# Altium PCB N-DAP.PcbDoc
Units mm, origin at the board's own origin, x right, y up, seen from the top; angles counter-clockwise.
Board outline 25.4 x 15.48 mm, 4 copper layers (Top Layer, GND PLANE, Signal Layer 1, Bottom Layer), stack 1.577 mm thick; 35 components, 41 nets, 128 pads, 69 vias.
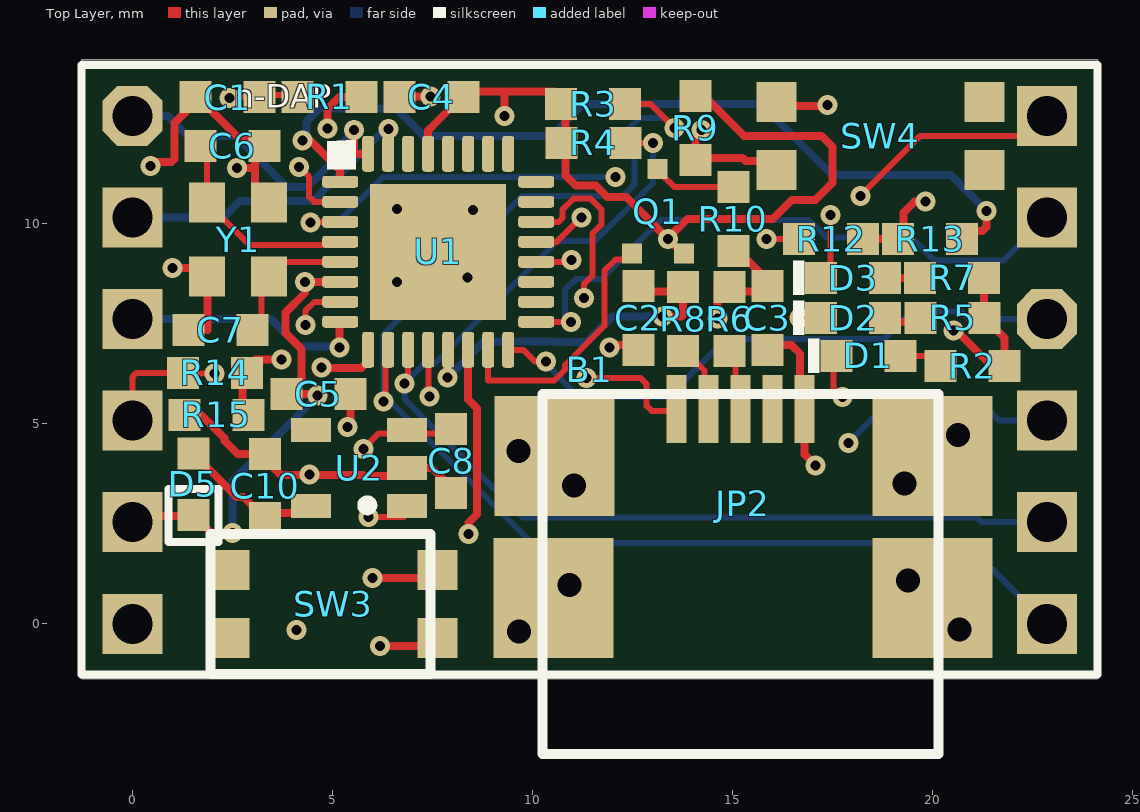
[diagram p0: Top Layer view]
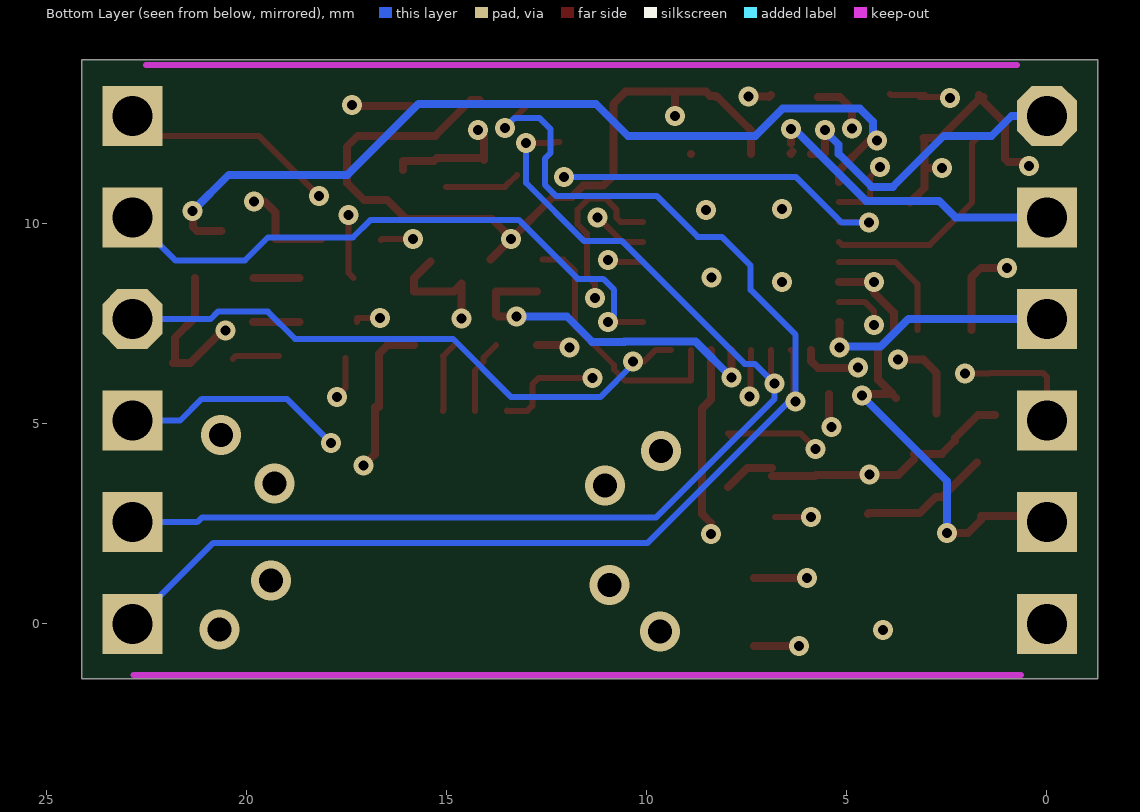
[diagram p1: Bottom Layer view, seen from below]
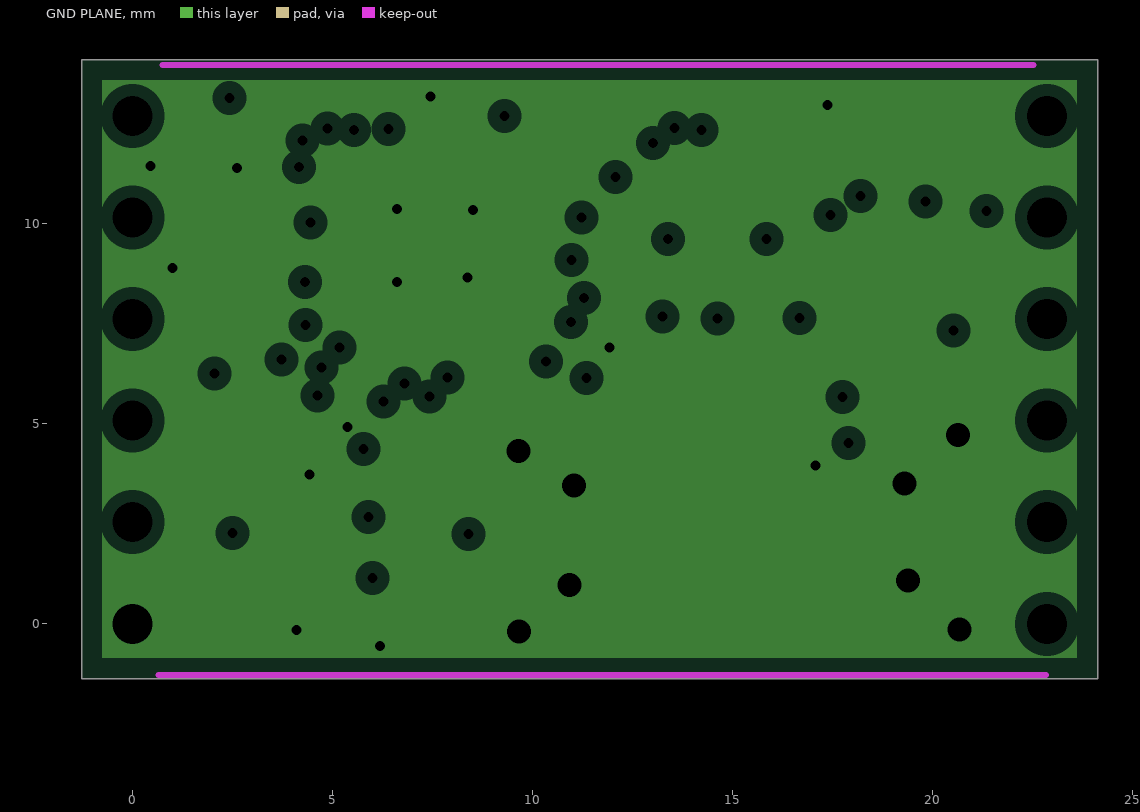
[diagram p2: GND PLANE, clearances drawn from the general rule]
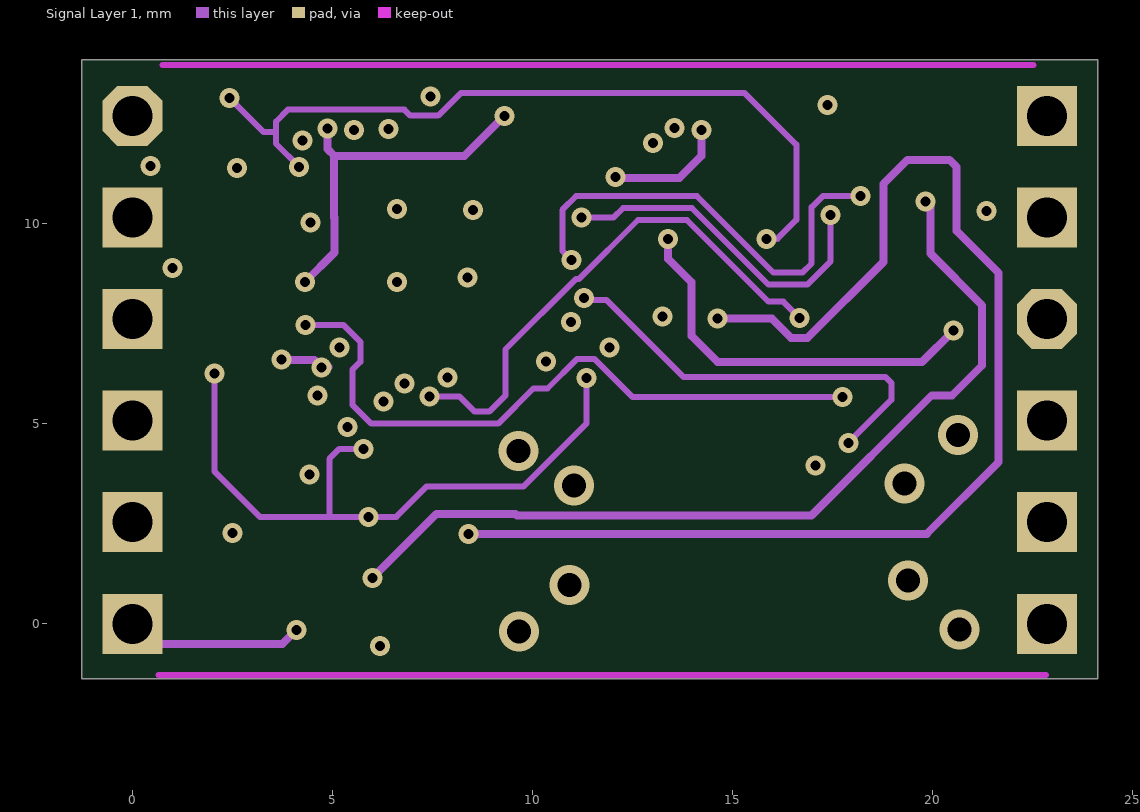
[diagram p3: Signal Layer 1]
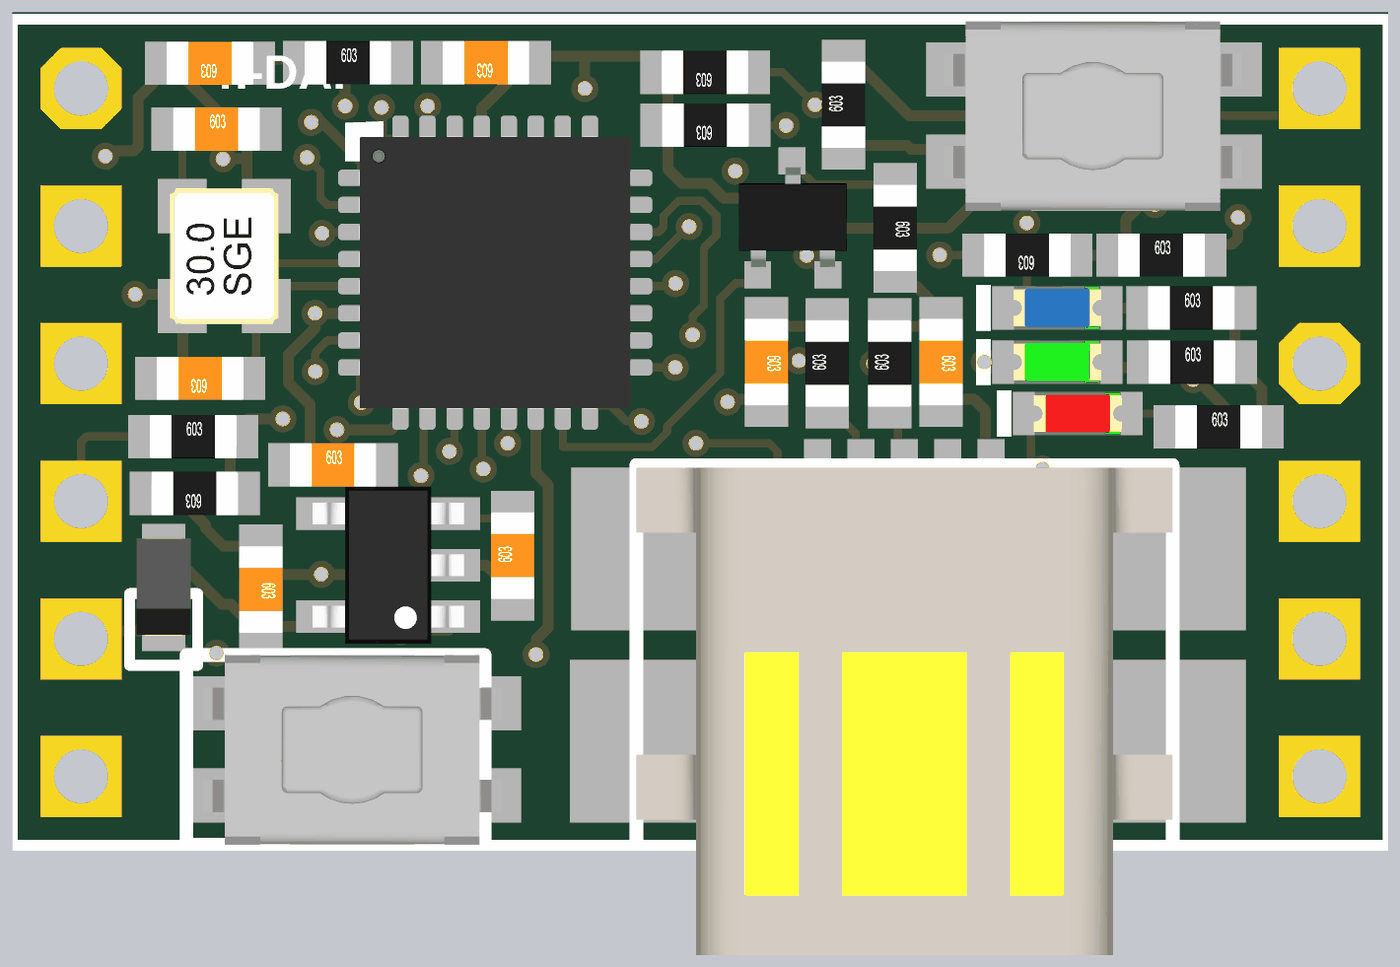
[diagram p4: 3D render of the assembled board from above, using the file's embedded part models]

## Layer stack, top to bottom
Top Solder: solder mask 0.0102, Solder Resist, Dk 3.5
Top Layer: signal copper 0.0356
Dielectric1: core 0.48, FR-4, Dk 4.8
GND PLANE: plane copper 0.036, net GND
Dielectric 4: prepreg 0.7, Dk 4.2
Signal Layer 1: signal copper 0.036
Dielectric 3: core 0.254, Dk 4.2
Bottom Layer: signal copper 0.0356
Bottom Solder: solder mask 0.0102, Solder Resist, Dk 3.5

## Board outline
-1.27,-1.37 24.13,-1.37 24.13,14.105 -1.27,14.105

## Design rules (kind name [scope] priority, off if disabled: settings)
Clearance "Clearance IN CLASS 1mm" [(InNetClass('CL-1mm'))] p1 off: gap=1 ignorepadtopadclearanceinfootprint=FALSE except(0: Arc-Hole Track-Hole SMDPad-Hole THPad-Hole Via-Hole Fill-Hole Poly-Hole Region-Hole Text-Hole)
Clearance Clearance_GND_PLANE [InNamedPolygon('GND_POLY_TOP')] p2 off: gap=0.4 ignorepadtopadclearanceinfootprint=FALSE except(0: Arc-Hole Track-Hole SMDPad-Hole THPad-Hole Via-Hole Fill-Hole Poly-Hole Region-Hole Text-Hole)
Clearance Clearance_+5V_POLY [InNamedPolygon('poly_+5V-bottom')] p3 off: gap=0.5 ignorepadtopadclearanceinfootprint=FALSE except(0: Arc-Hole Track-Hole SMDPad-Hole THPad-Hole Via-Hole Fill-Hole Poly-Hole Region-Hole Text-Hole)
Clearance [All] p4: gap=0.15 ignorepadtopadclearanceinfootprint=FALSE except(0: Arc-Hole Track-Hole SMDPad-Hole THPad-Hole Via-Hole Fill-Hole Poly-Hole Region-Hole Text-Hole)
MinimumAnnularRing [All] p1: minimumring=0.149
PlaneClearance [All] p1: clearance=0.3
PlaneConnect Plane_ConnectStyle_1 [(Name = 'C1-1') Or (Name = 'C1-2') Or (Name = 'C2-1') Or (Name = 'C2-2') Or (Name = 'C3-1') Or (Name = 'C3-2') Or (Name = 'C4-1') Or (Name = 'C4-2') Or (Name = 'C5-1') Or (Name = 'C5-2') Or (Name = 'C6-1') Or (Name = 'C6-2') Or (Name = 'C7-1')] p1 off: planeconnectstyle=Relief reliefexpansion=1.27 reliefentries=4 reliefconductorwidth=0.381 reliefairgap=0.508
PlaneConnect [All] p2: planeconnectstyle=Direct reliefexpansion=0.635 reliefentries=4 reliefconductorwidth=0.305 reliefairgap=0.254
PolygonConnect [All] p1: connectstyle=Direct reliefconductorwidth=0.254 reliefentries=4 polygonreliefangle="90 Angle" airgapwidth=0.254
RoomDefinition N-DAP [InComponentClass('N-DAP')] p1: confinementstyle=ConfineIn formatcopy=TRUE lockcomponents=FALSE outline -10.705,41.255 28.03,41.255 28.03,-1.925 -10.705,-1.925
RoutingVias VIASWITDTH2MM [(InNetClass('W-2mm'))] p1 off: holewidth=1 width=1.8 viastyle="Through Hole" minholewidth=0.4 minwidth=0.7 maxholewidth=1 maxwidth=1.8
RoutingVias VIASWITDTH1MM [(InNetClass('W-2mm'))] p2 off: holewidth=0.5 width=1 viastyle="Through Hole" minholewidth=0.5 minwidth=1 maxholewidth=0.5 maxwidth=1
RoutingVias VIASWITDTH1.5MM [(InNetClass('W-2mm'))] p3 off: holewidth=0.9 width=1.4 viastyle="Through Hole" minholewidth=0.9 minwidth=1.4 maxholewidth=0.9 maxwidth=1.4
RoutingVias [All] p4: holewidth=0.2 width=0.5 viastyle="Through Hole" minholewidth=0.2 minwidth=0.5 maxholewidth=4 maxwidth=2
SilkToSolderMaskClearance SilkscreenOverComponentPads [IsPad] p1: minsilkscreentomaskgap=0.254 clearancetoexposedcopper=TRUE
SolderMaskExpansion [All] p1: expansion=0
Width 12V_PLANE [(InNet('+12V')) and (IsPolygon)] p1 off: maxlimit=0.3 minlimit=0.2 preferedwidth=0.2
Width GND_PLANE [(InNet('GND'))  and (IsPolygon)] p2 off: maxlimit=0.3 minlimit=0.2 preferedwidth=0.2
Width WIDTH2MM [(InNetClass('W-2mm'))] p3 off: maxlimit=2 minlimit=0.25 preferedwidth=2
Width WIDTH1.5MM [(InNetClass('W-1.5mm'))] p4 off: maxlimit=2 minlimit=0.5 preferedwidth=1.5
Width "WIDTH 1MM" [(InNetClass('W-1mm'))] p5 off: maxlimit=2 minlimit=0.75 preferedwidth=1
Width WIDTH0.5MM [(InNetClass('W-0.5mm'))] p6 off: maxlimit=2 minlimit=0.25 preferedwidth=0.5
Width WIDTH0.25MM [(InNetClass('W-0.25mm'))] p7 off: maxlimit=2 minlimit=0.2 preferedwidth=0.25
Width [All] p8: maxlimit=2 minlimit=0.149 preferedwidth=0.15
27 further rules are at their usual default settings.

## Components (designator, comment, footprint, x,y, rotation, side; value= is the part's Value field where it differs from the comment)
B1 "N-DAP" N-DAP 0,12.7 r0 top locked
C1 "100nF" 0603_CAP 2.38,13.165 r180 top
C2 "18pF" 0603_CAP 12.65,7.65 r270 top
C3 "18pF" 0603_CAP 15.875,7.65 r270 top
C4 "100nF" 0603_CAP 7.475,13.175 r180 top
C5 "100nF" 0603_CAP 4.65,5.75 r0 top
C6 "33pF" 0603_CAP 2.5,11.95 r0 top
C7 "33pF" 0603_CAP 2.2,7.35 r180 top
C8 "1uF/MLCC" 0603_CAP 7.97,4.075 r90 top
C10 "1uF/MLCC" 0603_CAP 3.32,3.45 r270 top
D1 "LED_RED_0603" 0603_LED_RED 18.4,6.7 r180 top
D2 "LED_GRN_0603" 0603_LED_GRN 18.02,7.65 r180 top
D3 "LED_BLU_0603" 0603_LED_BLU 18.02,8.65 r180 top
D5 "NSR20F30NXT5G" 0603_DIODE-CDSU101A 1.525,3.5 r270 top
JP2 "USB-MINI-B" USB-MINI-B-HIR-UX60A-MB-5ST 16.85,4.55 r180 top
Q1 "BSS84,215" SOT323/SC70-3_SMALL 13.125,10.35 r180 top
R1 "10K" 0603_RES 4.925,13.175 r0 top
R2 "680R" 0603_RES 21,6.45 r0 top
R3 "10K" 0603_RES 11.52,13 r180 top
R4 "10K" 0603_RES 11.525,12.025 r180 top
R5 "470R" 0603_RES 20.505,7.65 r0 top
R6 "33R" 0603_RES 14.925,7.625 r90 top
R7 "470R" 0603_RES 20.495,8.65 r0 top
R8 "33R" 0603_RES 13.77,7.625 r90 top
R9 "10K" 0603_RES 14.075,12.4 r90 top
R10 "1.5K" 0603_RES 15.025,10.125 r270 top
R12 "0R" 0603_RES 17.47,9.625 r180 top
R13 "N.A." 0603_RES 19.945,9.625 r0 top
R14 "10K" 0603_RES 2.07,6.275 r0 top
R15 "18K" 0603_RES 2.1,5.225 r180 top
SW3 "EVQ-P2202M" BUTTON_4.7x3.5mm 5.125,0.35 r90 top
SW4 "EVQ-P2202M" BUTTON_4.7x3.5mm 18.8,12.05 r90 top
U1 "LPC11U35FHI33/501" QFN32_0.5MM_PAD 7.645,9.3 r0 top
U2 "TPS78233" SOT23-5_0.95MM-NOSILK 5.67,3.9 r90 top
Y1 "12MHz" CRY-SMD4-2.5X2MM 2.645,9.605 r90 top

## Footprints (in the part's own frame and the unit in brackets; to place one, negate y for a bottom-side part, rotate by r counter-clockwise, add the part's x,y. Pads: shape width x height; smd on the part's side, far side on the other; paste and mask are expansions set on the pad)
0603_CAP [mm]
  rect 0.8x0.8 smd mask+0: 1(-0.8,0) 2(0.8,0)
  body extent -0.8,-0.4 0.8,0.4, height 0.3
0603_DIODE-CDSU101A [mm]
  rect 0.8x0.8 smd mask+0: 1(-0.76,0) 2(0.786,0)
  silkscreen extent 0.13,-0.63 1.45,0.63, body extent -0.9,-0.5 0.9,0.5, height 0.85
0603_LED_BLU [mm]
  rect 0.8x0.8 smd mask+0: 1(-0.8,0) 2(0.8,0)
  silkscreen extent 1.22,-0.43 1.5,0.43, body extent -0.81,-0.4 0.81,0.4, height 0.6
0603_LED_GRN [mm]
  rect 0.8x0.8 smd mask+0: 1(-0.8,0) 2(0.8,0)
  silkscreen extent 1.22,-0.43 1.5,0.43, body extent -0.81,-0.4 0.81,0.4, height 0.6
0603_LED_RED [mm]
  rect 0.8x0.8 smd mask+0: 1(-0.8,0) 2(0.8,0)
  silkscreen extent 1.22,-0.43 1.5,0.43, body extent -0.81,-0.4 0.81,0.4, height 0.6
0603_RES [mm]
  rect 0.8x0.8 smd mask+0: 1(-0.8,0) 2(0.8,0)
  body extent -0.8,-0.4 0.8,0.4, height 0.3
BUTTON_4.7x3.5mm [mm] "TACTILE BUTTON 4.7x3.5mm Panasonic EVQ-P2202M"
  rect 1x1 smd: 1(-0.7,2.7) 2(1,2.7) 3(-0.7,-2.5) 4(1,-2.5)
  body extent -1.61,-2.63 1.89,2.87, height 2.15
CRY-SMD4-2.5X2MM [mm]
  rect 1x0.9 smd: 1(-0.925,-0.775) 2(0.925,-0.775) 3(0.925,0.775) 4(-0.925,0.775)
  body extent -1.35,-1.1 1.35,1.1, height 0.55
N-DAP [mm]
  oct 1.5x1.5 hole 1: 1(0,0) 10(22.86,-5.08)
  rect 1.5x1.5 hole 1: 2(0,-2.54) 3(0,-5.08) 4(0,-7.62) 5(0,-10.16) 6(0,-12.7) 7(22.86,-12.7) 8(22.86,-10.16) 9(22.86,-7.62) 11(22.86,-2.54) 12(22.86,0)
  silkscreen extent -1.27,-15.95 24.13,1.28, body extent 1.54,-4.44 121.83,177.96, height 0.55
QFN32_0.5MM_PAD [mm]
  rrect50% 0.9x0.3 smd mask+0: 1(-2.45,1.75) 2(-2.45,1.25) 3(-2.45,0.75) 4(-2.45,0.25) 5(-2.45,-0.25) 6(-2.45,-0.75) 7(-2.45,-1.25) 8(-2.45,-1.75) 17(2.45,-1.75) 18(2.45,-1.25) 19(2.45,-0.75) 20(2.45,-0.25) 21(2.45,0.25) 22(2.45,0.75) 23(2.45,1.25) 24(2.45,1.75)
  rrect50% 0.3x0.9 smd mask+0: 9(-1.75,-2.45) 10(-1.25,-2.45) 11(-0.75,-2.45) 12(-0.25,-2.45) 13(0.25,-2.45) 14(0.75,-2.45) 15(1.25,-2.45) 16(1.75,-2.45) 25(1.75,2.45) 26(1.25,2.45) 27(0.75,2.45) 28(0.25,2.45) 29(-0.25,2.45) 30(-0.75,2.45) 31(-1.25,2.45) 32(-1.75,2.45)
  rect 3.4x3.4 smd: 33(0,0)
  silkscreen extent -2.77,2.06 -2.06,2.79, body extent -2.51,-2.51 2.51,2.51, height 0.8
SOT23-5_0.95MM-NOSILK [mm]
  rect 0.6x1 smd: 1(-0.95,-1.2) 2(0,-1.2) 3(0.95,-1.2) 4(0.95,1.2) 5(-0.95,1.2)
  silkscreen extent -1.06,-0.33 -0.81,-0.08, body extent -1.45,-1.4 1.45,1.4, height 1.45
SOT323/SC70-3_SMALL [mm]
  rect 0.5x0.5 smd: 1(0.635,1.092) 2(-0.66,1.092) 3(0,-1.016)
  body extent -1.02,-1.02 0.98,1.08, height 1
USB-MINI-B-HIR-UX60A-MB-5ST [mm]
  rect 0.5x1.7 smd: 1(3.25,-0.825) 2(2.45,-0.825) 3(1.65,-0.825) 4(0.85,-0.825) 5(0.05,-0.825)
  rect 3x3 smd: 6(-3.15,3.9) 7(6.325,3.9) 8(-3.15,0.35) 9(6.3,0.35)
  body extent -3.3,-1.15 6.6,7.85, height 4.6

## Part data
C1 C4 C5: library part C, "CAPACITOR", Supplier Part Number 1=581-06035C104KAT2A
C2 C3: library part C, "CAPACITOR", Supplier Part Number 1=581-02013A180GAT2A
C6 C7: library part C, "CAPACITOR", Supplier Part Number 1=581-06035A330J
C8 C10: library part C, "CAPACITOR", Supplier Part Number 1=81-GCM188R71C105K64D
D1: library part LED, Supplier Part Number 1="Mouser - 720-LSL29K-G1J2-1-Z"
D2: library part LED, Supplier Part Number 1=720-LGL29KF2J124Z
D3: library part LED, Supplier Part Number 1=720-LBQ39GL2N2351
D5: library part DIODE, "DIODE", Supplier Part Number 1=863-NSR20F30NXT5G
JP2: Supplier Part Number 1=798-UX60A-MB-5ST
Q1: library part "mosfet BSS84", "POWER MOSFET-P SOT23", Supplier Part Number 1=621-BSS84W-F
R1 R3 R4 R9 R14: library part R, "RESISTOR", Supplier Part Number 1=667-ERJ-3EKF1002V
R2: library part R, "RESISTOR", Supplier Part Number 1=754-RR0816P-681D
R5 R7: library part R, "RESISTOR", Supplier Part Number 1=667-ERJ-3EKF4700V
R6 R8: library part R, "RESISTOR", Supplier Part Number 1=667-ERJ-3EKF33R0V
R10: library part R, "RESISTOR", Supplier Part Number 1=667-ERJ-3EKF1501V
R12 R13: library part R, "RESISTOR", Supplier Part Number 1=667-ERJ-3GEY0R00V
R15: library part R, "RESISTOR", Supplier Part Number 1=667-ERJ-3GEYJ183V
SW3 SW4: library part BUTTON_TACT, "BUTTON TACTILE", Supplier Part Number 1=667-EVQ-P2202M
U1: Supplier Part Number 1=771-LPC11U35FHI33501
U2: library part NCP702N, Supplier Part Number 1=595-TPS78233DDCR
Y1: library part XTAL_4PINS, "CRYSTAL", Supplier Part Number 1=717-8Z-12.000MAAJ-T

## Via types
v1: diameter 0.5, hole 0.25, Top Layer to Bottom Layer, tented both sides, 61 vias
v2: diameter 1, hole 0.6, Top Layer to Bottom Layer, tented both sides, 8 vias

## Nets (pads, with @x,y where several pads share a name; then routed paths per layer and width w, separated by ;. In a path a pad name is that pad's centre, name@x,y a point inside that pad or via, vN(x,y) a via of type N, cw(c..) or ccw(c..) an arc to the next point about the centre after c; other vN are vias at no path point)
3.3V: B1.5 C4.1 C5.1 D5.2 Q1.2 R1.2 R2.2 R3.2 R4.2 R5.2 R7.2 R9.2 U1.6 U1.29 | length 57.2
  Top Layer w0.2: B1.5@0,2.04 0.649,2.689 D5.2@1.65,2.689 ; D5.2@1.65,2.589 1.964,2.275 v1(2.5,2.275) ; C5.1@3.775,5.65 4.225,6.1 C5.1@4.225,6.125 ; C5.1@3.875,5.75 4.575,5.75 v1@4.625,5.7 ; C5.1@3.875,5.775 C5.1@4.225,6.125 ; v1(4.875,12.376) 4.875,12.875 5.175,13.175 R1.2 ; U1.6 v1(4.32,8.55) 4.32,8.276 3.825,7.781 3.825,7.268 4.225,6.868 C5.1@4.225,6.125 ; U1.29 7.395,12.335 7.46,12.4 ; 7.45,12.4 7.46,12.4 ; C4.1 8.235,13.175 7.46,12.4 ; C4.1@8.275,13.2 8.42,13.2 8.521,13.301 10.534,13.301 10.834,13 10.834,11.209 11.092,10.951 11.592,10.951 11.868,10.675 12.338,10.675 v1@13.382,9.632 ; v1(9.3,12.7) 9.3,13.275 9.325,13.3 ; v1@13.375,9.625 v1@13.382,9.632 ; Q1.2@13.905,9.108 v1(13.395,9.618) v1@13.382,9.632 ; R9.2@14.177,13.098 14.389,13.098 15.287,12.2 17.225,12.2 17.5,11.925 17.5,11.025 17.075,10.6 16.491,10.6 16.016,10.125 13.875,10.125 v1@13.382,9.632 ; v1(20.526,7.325) 20.603,7.325 21.404,6.525 R2.2@21.8,6.525 ; R7.2 21.295,7.655 21.8,7.15 R2.2@21.8,6.525 ; R2.2@21.85,6.525 R2.2@21.8,6.525
  Signal Layer 1 w0.2: v1(4.32,8.55) 5.05,9.28 5.05,10.157 5.045,10.162 5.045,11.7 ; v1(4.875,12.376) 4.875,11.87 5.045,11.7 ; v1(9.3,12.7) 8.3,11.7 5.045,11.7 ; v1(13.395,9.618) 13.395,9.118 13.975,8.538 13.975,7.2 14.634,6.541 19.742,6.541 v1(20.526,7.325)
  Bottom Layer w0.2: v1(2.5,2.275) 2.5,3.575 v1(4.625,5.7)
3.3V1: C10.2 D5.1 U2.5 | length 3.3
  Top Layer w0.2: D5.1@1.745,4.035 2.605,3.175 2.77,3.175 3.181,2.764 3.32,2.764 4.456,2.764 U2.5@4.47,2.75
ADC0: B1.12 U1.20 | length 18
  Top Layer w0.15: U1.20 10.925,9.05 v1(10.975,9.1) ; v1(18.2,10.7) 19.7,12.2 22.8,12.2 22.86,12.26 B1.12
  Signal Layer 1 w0.15: v1(10.975,9.1) 10.751,9.324 10.751,10.347 11.096,10.693 14.11,10.693 16.028,8.775 16.75,8.775 16.982,9.008 16.982,10.414 17.268,10.7 v1(18.2,10.7)
ADC1: B1.9 U1.22 | length 20.7
  Top Layer w0.15: U1.22 10.657,10.05 10.751,10.143 10.751,10.347 11.029,10.626 11.458,10.626 11.731,10.352 11.731,9.984 11.5,9.753 11.5,8.7 11.289,8.489 v1(11.289,8.15)
  Signal Layer 1 w0.15: v1(11.289,8.15) 11.289,8.139 11.25,8.1 11.85,8.1 13.775,6.175 18.825,6.175 18.975,6.025 18.975,5.6 v1(17.9,4.525)
  Bottom Layer w0.15: v1(17.9,4.525) 19,5.625 21.125,5.625 21.67,5.08 B1.9
ADC2: U1.23
ADC3: U1.24
ADC5/SWDIO: U1.25
BLUE: D3.2 U1.21 | length 11.5
  Top Layer w0.15: U1.21 10.611,9.55 11.211,10.151 v1(11.226,10.151) ; D3.2@17.334,8.65 17.457,8.773 v1(17.457,10.218)
  Signal Layer 1 w0.15: v1(11.226,10.151) 12.026,10.151 12.268,10.393 13.986,10.393 15.904,8.475 16.874,8.475 17.457,9.058 v1(17.457,10.218)
GND: B1.6 C1.2 C2.2 C3.2 C4.2 C5.2 C6.2 C7.2 C8.1 C10.1 JP2.5 JP2.6 JP2.7 JP2.8 JP2.9 R15.2 SW3.3 SW4.2 U1.33 U2.2 Y1.2 Y1.4 | length 29.5
  Top Layer w0.2: v1@0.45,11.425 v1(0.45,11.45) 0.55,11.55 0.975,11.55 1.05,11.625 1.05,12.52 C1.2@1.667,13.137 ; v1(1,8.9) 1.65,8.9 1.884,8.666 1.884,7.35 ; R15.2 1.714,5.225 2.3,4.639 2.3,4.575 2.625,4.25 C10.1 ; C1.2 1.639,13.165 C1.2@1.667,13.137 ; C1.2@1.695,13.22 1.695,13.165 C1.2@1.667,13.137 ; v1@2.595,11.425 v1(2.62,11.4) 3.062,11.4 ; C6.2@3.062,12.15 3.062,11.4 ; C6.2@3.081,12.15 2.654,12.15 C1.2@1.667,13.137 ; C10.1@3.32,4.11 3.705,3.725 v1@4.44,3.725 ; Y1.2 3.062,10.888 3.062,11.4 ; v1(4.434,3.73) v1@4.44,3.725 ; v1(5.375,4.925) 5.45,5 C5.2 ; v1(6.195,-0.55) SW3.3@7.32,-0.55 ; U2.2@6.87,3.7 5.795,3.7 5.77,3.725 v1@4.44,3.725 ; U2.2 7.485,3.9 C8.1@7.97,3.415 ; C4.2@6.9,13.22 6.945,13.175 v1(7.45,13.176) ; v1(11.933,6.912) 11.986,6.964 C2.2@12.745,6.964 ; C3.2@15.82,6.964 16.48,6.964 16.695,6.749 JP2.5@16.695,5.425 ; SW4.2@15.895,12.95 17.35,12.95 v1(17.375,12.975) ; JP2.5@16.8,5.425 16.8,4.237 v1(17.081,3.956)
  Signal Layer 1 w0.2: B1.6@0,-0.5 3.75,-0.5 v1(4.1,-0.15)
  other v1: 6.62,8.55 8.375,8.65 8.52,10.35 6.62,10.375
  other v2: 9.67,-0.193 20.68,-0.138 10.933,0.969 19.396,1.079 11.041,3.454 19.306,3.507 9.65,4.325 20.64,4.719
GREEN: D2.2 U1.12 | length 14.9
  Top Layer w0.15: U1.12 7.388,6.843 7.388,6.485 7.4,6.472 7.4,5.7 v1(7.425,5.675) ; v1(16.675,7.65) 17.234,7.65 17.25,7.634 D2.2@17.25,7.55
  Signal Layer 1 w0.15: v1(7.425,5.675) 8.182,5.675 8.557,5.3 8.922,5.3 9.325,5.703 9.325,6.858 11.092,8.625 11.172,8.625 12.64,10.093 13.862,10.093 15.904,8.05 16.275,8.05 v1(16.675,7.65)
LPC11-D+: JP2.3 R6.1 | length 1.8
  Top Layer w0.15: R6.1@14.82,6.965 15.095,6.69 15.079,6.673 15.079,5.346 15.095,5.33 JP2.3@15.1,5.325
LPC11-D-: JP2.2 R8.1 | length 1.9
  Top Layer w0.15: R8.1@13.77,6.965 R8.1@14.082,6.653 ; R8.1@14.078,6.648 14.082,6.644 14.082,6.551 14.3,6.333 14.3,5.425 JP2.2@14.3,5.325
LPC11-USBD+: C3.1 R6.2 R10.2 U1.14 | length 38.9
  Top Layer w0.2: U1.14 8.395,5.604 8.62,5.379 8.62,2.745 8.4,2.525 v1(8.4,2.25) ; v1(14.626,7.625) 14.626,8.505 14.82,8.311 C3.1@15.82,8.311 ; R10.2@15.41,9.053 15.82,8.643 C3.1@15.82,8.31
  Signal Layer 1 w0.2: v1(8.4,2.25) 19.861,2.25 21.65,4.039 21.65,8.775 20.6,9.825 20.6,11.425 20.425,11.6 19.375,11.6 18.775,11 18.775,9.043 16.882,7.15 16.468,7.15 15.993,7.625 v1(14.626,7.625)
LPC11-USBD-: C2.1 R8.2 U1.13 | length 8.9
  Top Layer w0.2: v1(7.875,6.15) 7.875,6.83 U1.13 ; C2.1@12.745,8.311 13.77,8.311 13.77,7.721 13.725,7.675 v1(13.251,7.675)
  Bottom Layer w0.2: v1(7.875,6.15) 8.779,7.054 10.552,7.054 10.555,7.05 11.365,7.05 11.99,7.675 v1(13.251,7.675)
LPC11-USBSCON: Q1.1 U1.15 | length 6.6
  Top Layer w0.15: U1.15 8.895,6.08 8.896,6.079 10.541,6.079 10.82,6.357 10.82,6.47 11.8,7.45 11.8,8.824 12.084,9.108 Q1.1@12.61,9.108
LPC11-USBVBUS: R14.2 R15.1 U1.9 | length 4.9
  Top Layer w0.2: R15.1@2.756,5.25 2.756,6.275 3.081,6.6 v1(3.725,6.6) ; v1@4.751,6.4 5.725,6.4 5.895,6.57 U1.9
  Signal Layer 1 w0.2: v1(3.725,6.6) 4.551,6.6 v1@4.75,6.4 ; v1(4.725,6.4) v1@4.75,6.4 ; v1@4.9,6.425 4.875,6.4 v1@4.75,6.4
MOSI0: U1.18
NetD1_1: D1.1 R2.1 | length 1.2
  Top Layer w0.15: D1.1 20.275,6.7 R2.1@20.35,6.625
NetD2_1: D2.1 R5.1 | length 1.2
  Top Layer w0.2: D2.1@18.68,7.55 R5.1@19.845,7.55
NetD3_1: D3.1 R7.1 | length 1.2
  Top Layer w0.2: D3.1@18.68,8.65 R7.1@19.835,8.65
NetQ1_3: Q1.3 R10.1 | length 1.9
  Top Layer w0.15: Q1.3@13.245,11.216 13.418,11.043 ; 13.425,11.05 13.55,10.925 R10.1
NetR9_1: R9.1 SW4.1 U1.3 | length 15
  Top Layer w0.15: v1(4.45,10.026) 4.475,10.05 U1.3 ; v1(12.075,11.175) v1@12.091,11.191
  Top Layer w0.2: R9.1 R9.1@14.075,11.65 ; v1(14.225,12.35) 14.075,12.2 R9.1@14.075,11.65 ; SW4.1 16.1,11.575 15.325,11.575 15.25,11.65 R9.1@14.075,11.65
  Signal Layer 1 w0.2: v1@12.075,11.15 13.675,11.15 14.225,11.7 v1(14.225,12.35)
  Bottom Layer w0.15: v1(4.45,10.026) 5.126,10.026 6.275,11.175 v1(12.075,11.175)
NetR12_1: R12.1 R13.1 SW3.4 | length 25.8
  Top Layer w0.2: v1(6,1.15) 6,1.175 6.025,1.15 SW3.4@7.32,1.15 ; R12.1@18.13,9.625 19.285,9.625 19.285,10.285 19.559,10.559 v1(19.825,10.559)
  Signal Layer 1 w0.2: v1(6,1.15) 7.6,2.75 9.575,2.75 9.621,2.704 16.979,2.704 19.986,5.711 20.495,5.711 21.245,6.461 21.245,7.96 19.95,9.255 v1@19.95,10.45
NetR13_2: R13.2 U1.1 | length 22.2
  Top Layer w0.2: v1(4.25,12.076) 4.45,12.076 5.195,11.331 U1.1 ; R13.2@20.631,9.825 21.25,9.825 21.35,9.925 21.35,10.325 v1(21.358,10.318)
  Bottom Layer w0.2: v1(4.25,12.076) 4.25,12.108 4.35,12.208 4.35,12.557 4.668,12.876 6.605,12.876 7.28,12.2 10.475,12.2 11.275,13 15.708,13 17.483,11.225 20.45,11.225 v1(21.358,10.318) ; v1@21.282,10.243 v1@21.35,10.175
PIO0_5/SWCLK: U1.19
PIO1_1: U1.28
RED: D1.2 U1.7 | length 19.1
  Top Layer w0.15: v1(4.325,7.475) 4.325,7.822 4.553,8.05 U1.7 ; D1.2@17.534,6.65 17.534,5.891 v1(17.75,5.675)
  Signal Layer 1 w0.15: v1(4.325,7.475) 5.272,7.475 5.697,7.05 5.697,6.55 5.5,6.353 5.5,5.475 5.975,5 9.145,5 10.025,5.881 10.377,5.881 11.122,6.625 11.548,6.625 12.498,5.675 v1(17.75,5.675)
RESET-IO: U1.30
RESET-LPC11: C1.1 R1.1 R12.2 U1.2 | length 23.8
  Top Layer w0.15: v1(2.425,13.15) 2.44,13.165 C1.1 ; C1.1@3.041,13.22 3.895,13.22 R1.1@3.92,13.245 ; v1(4.17,11.425) 4.42,11.175 4.42,10.675 4.545,10.55 U1.2 ; v1(15.85,9.625) 16.625,9.625 R12.2@16.65,9.6
  Signal Layer 1 w0.15: v1(2.425,13.15) 3.275,12.3 3.591,12.3 ; v1(4.17,11.425) 3.591,12.005 3.591,12.3 ; v1(15.85,9.625) 16.125,9.625 16.6,10.1 16.6,11.976 15.301,13.275 8.221,13.275 7.647,12.701 6.95,12.701 6.8,12.851 3.887,12.851 3.591,12.554 3.591,12.3
RESET-TGT: B1.3 U1.8 | length 6.1
  Top Layer w0.2: v1(5.175,6.9) 5.175,7.53 U1.8
  Bottom Layer w0.2: B1.3 3.463,7.62 4.157,6.925 5.15,6.925 v1(5.175,6.9)
RXD0: B1.2 U1.31 | length 7.8
  Top Layer w0.2: U1.31@6.35,11.805 6.4,11.755 U1.31 ; U1.31@6.398,12.007 v1(6.398,12.375)
  Bottom Layer w0.2: B1.2 2.276,10.16 2.691,10.575 4.522,10.575 6.322,12.375 v1(6.398,12.375)
SCL1: B1.7 R3.1 U1.10 | length 34.5
  Top Layer w0.15: v1(6.275,5.55) 6.325,5.6 6.325,6.78 U1.10 ; R3.1@12.18,13 12.95,13 v1(13.55,12.4)
  Bottom Layer w0.15: v1(13.55,12.4) 13.309,12.641 12.679,12.641 12.401,12.363 12.401,11.771 12.55,11.622 12.55,10.978 12.272,10.7 9.753,10.7 8.728,9.675 8.125,9.675 7.402,8.952 7.402,8.348 6.275,7.222 v1(6.275,5.55) 6.454,5.55 9.98,2.025 20.835,2.025 B1.7
SDA1: B1.8 R4.1 U1.11 | length 28.7
  Top Layer w0.15: v1@6.895,6 U1.11 ; R4.1@12.18,12.05 R4.1@12.325,12.05 ; R4.1 12.334,12.016 v1(13.015,12.016)
  Bottom Layer w0.15: v1(13.015,12.016) 13.015,11.019 11.571,9.575 10.628,9.575 7.553,6.5 7.3,6.5 v1(6.8,6) 6.8,5.629 9.774,2.655 21.124,2.655 21.239,2.54 B1.8
SLEEP-REQ: U1.27
SWCLK: B1.10 U1.16 | length 14.9
  Top Layer w0.15: U1.16 9.775,6.85 10.071,6.554 v1(10.345,6.554)
  Bottom Layer w0.15: v1(10.345,6.554) 10.345,6.485 11.155,5.675 13.397,5.675 14.844,7.122 18.795,7.122 19.473,7.8 20.723,7.8 20.903,7.62 B1.10
SWDIO: B1.11 U1.17 | length 15.4
  Top Layer w0.15: U1.17 v1(10.97,7.55)
  Bottom Layer w0.15: v1(10.97,7.55) 10.814,7.706 10.814,8.347 11.092,8.625 11.73,8.625 13.205,10.1 16.903,10.1 17.343,9.66 19.47,9.66 20.045,9.086 21.786,9.086 B1.11
TXD0: B1.1 U1.32 | length 8
  Top Layer w0.2: v1(5.545,12.35) 5.545,11.77 5.565,11.75 U1.32
  Bottom Layer w0.2: B1.1 0.877,12.7 1.377,12.2 2.575,12.2 3.85,10.925 4.377,10.925 5.202,11.75 5.202,11.977 5.545,12.32 v1(5.545,12.35)
VBUS: B1.4 C8.2 JP2.1 R14.1 U2.1 U2.3 | length 26.2
  Top Layer w0.15: B1.4 0,6.175 0.1,6.275 1.41,6.275 1.434,6.25 v1(2.05,6.25) ; v1(5.775,4.375) 6.161,4.761 7.97,4.761 C8.2@7.859,4.65 ; v1(5.9,2.675) U2.1@6.795,2.675 ; v1(11.351,6.15) 12.701,6.15 12.859,5.992 12.859,5.449 12.984,5.325 13.5,5.325 JP2.1@13.495,5.33
  Signal Layer 1 w0.15: v1(2.05,6.25) 2.05,3.813 3.188,2.675 4.925,2.675 ; v1@5.792,4.375 v1(5.775,4.375) 5.175,4.375 4.925,4.125 4.925,2.675 ; v1(11.351,6.15) 11.351,5.001 9.777,3.427 7.352,3.427 6.6,2.675 v1(5.9,2.675) 4.925,2.675
WAKE-REQ: U1.26 | length 0
X5: C6.1 U1.4 Y1.3 | length 5.5
  Top Layer w0.15: C6.1@1.735,12.15 1.87,12.015 Y1.3 2.925,9.475 5.12,9.475 U1.4
X6: C7.1 U1.5 Y1.1 | length 3.3
  Top Layer w0.15: C7.1@3.23,7.35 3.23,8.49 Y1.1 3.79,9.05 U1.5
pads on no net: JP2.4 SW3.1 SW3.2 SW4.3 SW4.4 U2.4

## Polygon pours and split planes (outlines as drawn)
GND on GND PLANE (split plane): 23.62,-0.86 -0.76,-0.86 -0.76,13.595 23.62,13.595

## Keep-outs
Keep-Out Layer:
  lines w0.15: 0.65,-1.275 22.835,-1.275 ; 0.75,13.975 22.525,13.975

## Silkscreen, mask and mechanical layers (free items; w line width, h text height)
Mechanical 1:
  lines w0.15: 0,-1.925 0,14.05 16,14.05 16,-1.925 0,-1.925
Mechanical 2:
  lines w0.15: 196.749,90.961 196.794,91.006
Mechanical 3:
  the board outline again, w0.2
